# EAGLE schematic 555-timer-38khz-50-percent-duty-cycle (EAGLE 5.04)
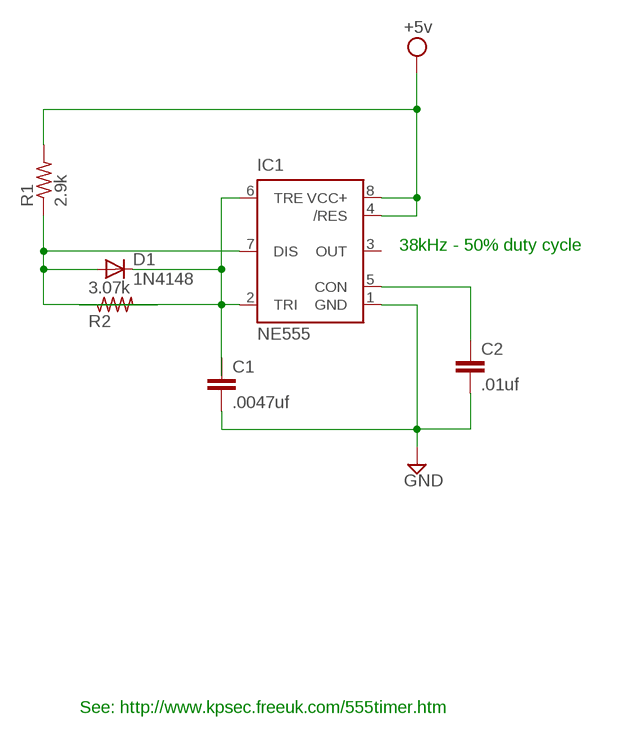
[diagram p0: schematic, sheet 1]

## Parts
C1  .0047uf  CAPPTH  [CAP-PTH-SMALL]
C2  .01uf  CAPPTH  [CAP-PTH-SMALL]
D1  1N4148  1N4148DO35-10  [DO35-10]
IC1  NE555  [DIL-08]
R1  2.9k  R-US_V234/12  [V234/12]
R2  3.07k  R-US_V234/12  [V234/12]

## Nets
GND: C1.2 C2.2 IC1.1(GND)
N$1: D1.C IC1.2(TRI) IC1.6(TRE) R2.1
N$3: D1.A IC1.7(DIS) R1.1 R2.2
N$5: C2.1 IC1.5(CON)
VCC: IC1.4(/RES) IC1.8(VCC+) R1.2 ; supply symbol labelled +5v
Unconnected: C1.1 IC1.3(OUT)

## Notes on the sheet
- 38kHz - 50% duty cycle
- See: http://www.kpsec.freeuk.com/555timer.htm

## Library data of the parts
C1 C2 = SparkFun:CAP: Capacitor
D1 = diode:1N4148: DIODE
IC1 = st-microelectronics:NE555: General purpose bipolar Timer
R1 R2 = resistor:R-US_: RESISTOR, American symbol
